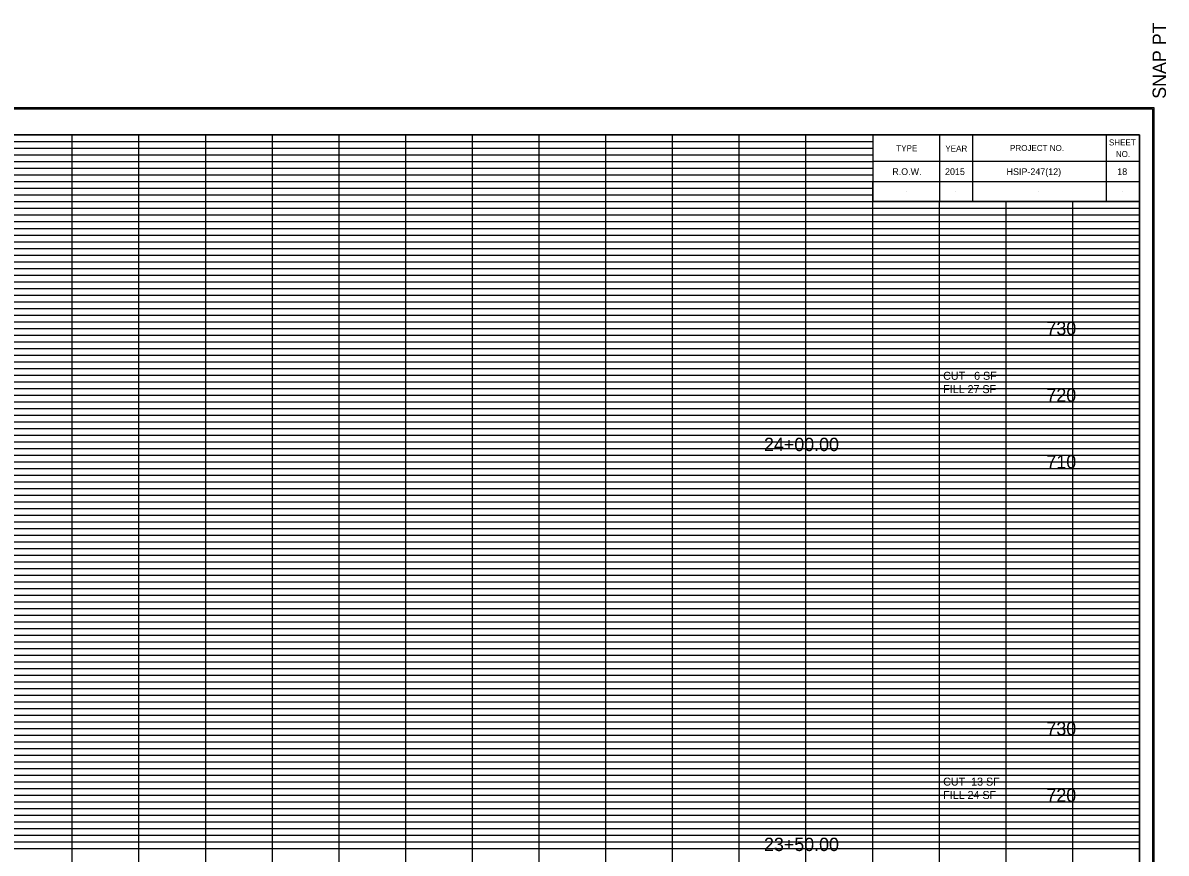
# Model space of a CAD drawing. Extents: x -200 to 1324, y -325 to 1497.
# Drawn here: x 1152.6 to 1324, y 1372.3 to 1496.8 of the extents above; entities that cross this region are included whole.
import ezdxf

# ---------------------------------------------------------------- set-up
doc = ezdxf.new("R2010")
doc.units = 0
for name, color, linetype in [('DESIGN - SCRATCH - User 1', 7, 'Continuous'), ('DESIGN - SHEET - Corner Text', 7, 'Continuous'), ('DESIGN - SHEET - Light Grid', 7, 'Continuous'), ('DESIGN - SHEET - Linework', 7, 'Continuous'), ('DESIGN - SHEET - Plot Shape', 7, 'Continuous'), ('DESIGN - TYPICAL - Text', 7, 'Continuous')]:
    doc.layers.add(name, color=color, linetype=linetype)

msp = doc.modelspace()

# ---------------------------------------------------------------- linework, layer by layer
at = {"layer": 'DESIGN - SCRATCH - User 1'}
for p, q in [((1285, 1474.5), (1285, 1474.5)), ((1292.4, 1474.5), (1292.4, 1474.5)), ((1304.9, 1474.5), (1304.9, 1474.5)), ((1317.4, 1474.5), (1317.4, 1474.5)), ((1285, 1471.5), (1285, 1471.5)), ((1292.4, 1471.5), (1292.4, 1471.5)), ((1304.9, 1471.5), (1304.9, 1471.5)), ((1317.4, 1471.5), (1317.4, 1471.5))]:
    msp.add_line(p, q, dxfattribs=at)
at = {"layer": 'DESIGN - SHEET - Light Grid'}
for p, q in [((1080, 1479), (1160, 1479)), ((1080, 1478), (1160, 1478)), ((1160, 1479), (1240, 1479)), ((1160, 1478), (1240, 1478)), ((1240, 1479), (1280, 1479)), ((1240, 1478), (1280, 1478)), ((1080, 1477), (1160, 1477)), ((1080, 1476), (1160, 1476)), ((1160, 1477), (1240, 1477)), ((1160, 1476), (1240, 1476)), ((1240, 1477), (1280, 1477)), ((1240, 1476), (1280, 1476)), ((1080, 1475), (1160, 1475)), ((1160, 1475), (1240, 1475)), ((1240, 1475), (1280, 1475)), ((1080, 1474), (1160, 1474)), ((1080, 1473), (1160, 1473)), ((1160, 1474), (1240, 1474)), ((1160, 1473), (1240, 1473)), ((1240, 1474), (1280, 1474)), ((1240, 1473), (1280, 1473)), ((1080, 1472), (1160, 1472)), ((1080, 1471), (1160, 1471)), ((1160, 1472), (1240, 1472)), ((1160, 1471), (1240, 1471)), ((1240, 1472), (1280, 1472)), ((1240, 1471), (1280, 1471)), ((1080, 1469), (1160, 1469)), ((1160, 1469), (1240, 1469)), ((1240, 1469), (1320, 1469)), ((1080, 1468), (1160, 1468)), ((1160, 1468), (1240, 1468)), ((1240, 1468), (1320, 1468)), ((1080, 1467), (1160, 1467)), ((1080, 1466), (1160, 1466)), ((1160, 1467), (1240, 1467)), ((1160, 1466), (1240, 1466)), ((1240, 1467), (1320, 1467)), ((1240, 1466), (1320, 1466)), ((1080, 1465), (1160, 1465)), ((1080, 1464), (1160, 1464)), ((1160, 1465), (1240, 1465)), ((1160, 1464), (1240, 1464)), ((1240, 1465), (1320, 1465)), ((1240, 1464), (1320, 1464)), ((1080, 1463), (1160, 1463)), ((1160, 1463), (1240, 1463)), ((1240, 1463), (1320, 1463)), ((1080, 1462), (1160, 1462)), ((1080, 1461), (1160, 1461)), ((1160, 1462), (1240, 1462)), ((1160, 1461), (1240, 1461)), ((1240, 1462), (1320, 1462)), ((1240, 1461), (1320, 1461)), ((1080, 1459), (1160, 1459)), ((1160, 1459), (1240, 1459)), ((1240, 1459), (1320, 1459)), ((1080, 1458), (1160, 1458)), ((1080, 1457), (1160, 1457)), ((1160, 1458), (1240, 1458)), ((1160, 1457), (1240, 1457)), ((1240, 1458), (1320, 1458)), ((1240, 1457), (1320, 1457)), ((1080, 1456), (1160, 1456)), ((1160, 1456), (1240, 1456)), ((1240, 1456), (1320, 1456)), ((1080, 1455), (1160, 1455)), ((1080, 1454), (1160, 1454)), ((1160, 1455), (1240, 1455)), ((1160, 1454), (1240, 1454)), ((1240, 1455), (1320, 1455)), ((1240, 1454), (1320, 1454)), ((1080, 1453), (1160, 1453)), ((1080, 1452), (1160, 1452)), ((1160, 1453), (1240, 1453)), ((1160, 1452), (1240, 1452)), ((1240, 1453), (1320, 1453)), ((1240, 1452), (1320, 1452)), ((1080, 1451), (1160, 1451)), ((1160, 1451), (1240, 1451)), ((1240, 1451), (1320, 1451)), ((1080, 1449), (1160, 1449)), ((1160, 1449), (1240, 1449)), ((1240, 1449), (1320, 1449)), ((1080, 1448), (1160, 1448)), ((1080, 1447), (1160, 1447)), ((1160, 1448), (1240, 1448)), ((1160, 1447), (1240, 1447)), ((1240, 1448), (1320, 1448)), ((1240, 1447), (1320, 1447)), ((1080, 1446), (1160, 1446)), ((1080, 1445), (1160, 1445)), ((1160, 1446), (1240, 1446)), ((1160, 1445), (1240, 1445)), ((1240, 1446), (1320, 1446)), ((1240, 1445), (1320, 1445)), ((1080, 1444), (1160, 1444)), ((1160, 1444), (1240, 1444)), ((1240, 1444), (1320, 1444)), ((1080, 1443), (1160, 1443)), ((1080, 1442), (1160, 1442)), ((1160, 1443), (1240, 1443)), ((1160, 1442), (1240, 1442)), ((1240, 1443), (1320, 1443)), ((1240, 1442), (1320, 1442)), ((1080, 1441), (1160, 1441)), ((1160, 1441), (1240, 1441)), ((1240, 1441), (1320, 1441)), ((1080, 1439), (1160, 1439)), ((1160, 1439), (1240, 1439)), ((1240, 1439), (1320, 1439)), ((1080, 1438), (1160, 1438)), ((1080, 1437), (1160, 1437)), ((1160, 1438), (1240, 1438)), ((1160, 1437), (1240, 1437)), ((1240, 1438), (1320, 1438)), ((1240, 1437), (1320, 1437)), ((1080, 1436), (1160, 1436)), ((1080, 1435), (1160, 1435)), ((1160, 1436), (1240, 1436)), ((1160, 1435), (1240, 1435)), ((1240, 1436), (1320, 1436)), ((1240, 1435), (1320, 1435)), ((1080, 1434), (1160, 1434)), ((1080, 1433), (1160, 1433)), ((1160, 1434), (1240, 1434)), ((1160, 1433), (1240, 1433)), ((1240, 1434), (1320, 1434)), ((1240, 1433), (1320, 1433)), ((1080, 1432), (1160, 1432)), ((1160, 1432), (1240, 1432)), ((1240, 1432), (1320, 1432)), ((1080, 1431), (1160, 1431)), ((1160, 1431), (1240, 1431)), ((1240, 1431), (1320, 1431)), ((1080, 1429), (1160, 1429)), ((1080, 1428), (1160, 1428)), ((1160, 1429), (1240, 1429)), ((1160, 1428), (1240, 1428)), ((1240, 1429), (1320, 1429)), ((1240, 1428), (1320, 1428)), ((1080, 1427), (1160, 1427)), ((1160, 1427), (1240, 1427)), ((1240, 1427), (1320, 1427)), ((1080, 1426), (1160, 1426)), ((1080, 1425), (1160, 1425)), ((1160, 1426), (1240, 1426)), ((1160, 1425), (1240, 1425)), ((1240, 1426), (1320, 1426)), ((1240, 1425), (1320, 1425)), ((1080, 1424), (1160, 1424)), ((1080, 1423), (1160, 1423)), ((1160, 1424), (1240, 1424)), ((1160, 1423), (1240, 1423)), ((1240, 1424), (1320, 1424)), ((1240, 1423), (1320, 1423)), ((1080, 1422), (1160, 1422)), ((1080, 1421), (1160, 1421)), ((1160, 1422), (1240, 1422)), ((1160, 1421), (1240, 1421)), ((1240, 1422), (1320, 1422)), ((1240, 1421), (1320, 1421)), ((1080, 1419), (1160, 1419)), ((1080, 1418), (1160, 1418)), ((1160, 1419), (1240, 1419)), ((1160, 1418), (1240, 1418)), ((1240, 1419), (1320, 1419)), ((1240, 1418), (1320, 1418)), ((1080, 1417), (1160, 1417)), ((1080, 1416), (1160, 1416)), ((1160, 1417), (1240, 1417)), ((1160, 1416), (1240, 1416)), ((1240, 1417), (1320, 1417)), ((1240, 1416), (1320, 1416)), ((1080, 1415), (1160, 1415)), ((1160, 1415), (1240, 1415)), ((1240, 1415), (1320, 1415)), ((1080, 1414), (1160, 1414)), ((1080, 1413), (1160, 1413)), ((1160, 1414), (1240, 1414)), ((1160, 1413), (1240, 1413)), ((1240, 1414), (1320, 1414)), ((1240, 1413), (1320, 1413)), ((1080, 1412), (1160, 1412)), ((1080, 1411), (1160, 1411)), ((1160, 1412), (1240, 1412)), ((1160, 1411), (1240, 1411)), ((1240, 1412), (1320, 1412)), ((1240, 1411), (1320, 1411)), ((1080, 1409), (1160, 1409)), ((1160, 1409), (1240, 1409)), ((1240, 1409), (1320, 1409)), ((1080, 1408), (1160, 1408)), ((1160, 1408), (1240, 1408)), ((1240, 1408), (1320, 1408)), ((1080, 1407), (1160, 1407)), ((1080, 1406), (1160, 1406)), ((1160, 1407), (1240, 1407)), ((1160, 1406), (1240, 1406)), ((1240, 1407), (1320, 1407)), ((1240, 1406), (1320, 1406)), ((1080, 1405), (1160, 1405)), ((1080, 1404), (1160, 1404)), ((1160, 1405), (1240, 1405)), ((1160, 1404), (1240, 1404)), ((1240, 1405), (1320, 1405)), ((1240, 1404), (1320, 1404)), ((1080, 1403), (1160, 1403)), ((1160, 1403), (1240, 1403)), ((1240, 1403), (1320, 1403)), ((1080, 1402), (1160, 1402)), ((1080, 1401), (1160, 1401)), ((1160, 1402), (1240, 1402)), ((1160, 1401), (1240, 1401)), ((1240, 1402), (1320, 1402)), ((1240, 1401), (1320, 1401)), ((1080, 1399), (1160, 1399)), ((1160, 1399), (1240, 1399)), ((1240, 1399), (1320, 1399)), ((1080, 1398), (1160, 1398)), ((1080, 1397), (1160, 1397)), ((1160, 1398), (1240, 1398)), ((1160, 1397), (1240, 1397)), ((1240, 1398), (1320, 1398)), ((1240, 1397), (1320, 1397)), ((1080, 1396), (1160, 1396)), ((1160, 1396), (1240, 1396)), ((1240, 1396), (1320, 1396)), ((1080, 1395), (1160, 1395)), ((1080, 1394), (1160, 1394)), ((1160, 1395), (1240, 1395)), ((1160, 1394), (1240, 1394)), ((1240, 1395), (1320, 1395)), ((1240, 1394), (1320, 1394)), ((1080, 1393), (1160, 1393)), ((1080, 1392), (1160, 1392)), ((1160, 1393), (1240, 1393)), ((1160, 1392), (1240, 1392)), ((1240, 1393), (1320, 1393)), ((1240, 1392), (1320, 1392)), ((1080, 1391), (1160, 1391)), ((1160, 1391), (1240, 1391)), ((1240, 1391), (1320, 1391)), ((1080, 1389), (1160, 1389)), ((1160, 1389), (1240, 1389)), ((1240, 1389), (1320, 1389)), ((1080, 1388), (1160, 1388)), ((1080, 1387), (1160, 1387)), ((1160, 1388), (1240, 1388)), ((1160, 1387), (1240, 1387)), ((1240, 1388), (1320, 1388)), ((1240, 1387), (1320, 1387)), ((1080, 1386), (1160, 1386)), ((1080, 1385), (1160, 1385)), ((1160, 1386), (1240, 1386)), ((1160, 1385), (1240, 1385)), ((1240, 1386), (1320, 1386)), ((1240, 1385), (1320, 1385)), ((1080, 1384), (1160, 1384)), ((1160, 1384), (1240, 1384)), ((1240, 1384), (1320, 1384)), ((1080, 1383), (1160, 1383)), ((1080, 1382), (1160, 1382)), ((1160, 1383), (1240, 1383)), ((1160, 1382), (1240, 1382)), ((1240, 1383), (1320, 1383)), ((1240, 1382), (1320, 1382)), ((1080, 1381), (1160, 1381)), ((1160, 1381), (1240, 1381)), ((1240, 1381), (1320, 1381)), ((1080, 1379), (1160, 1379)), ((1160, 1379), (1240, 1379)), ((1240, 1379), (1320, 1379)), ((1080, 1378), (1160, 1378)), ((1080, 1377), (1160, 1377)), ((1160, 1378), (1240, 1378)), ((1160, 1377), (1240, 1377)), ((1240, 1378), (1320, 1378)), ((1240, 1377), (1320, 1377)), ((1080, 1376), (1160, 1376)), ((1080, 1375), (1160, 1375)), ((1160, 1376), (1240, 1376)), ((1160, 1375), (1240, 1375)), ((1240, 1376), (1320, 1376)), ((1240, 1375), (1320, 1375)), ((1080, 1374), (1160, 1374)), ((1080, 1373), (1160, 1373)), ((1160, 1374), (1240, 1374)), ((1160, 1373), (1240, 1373)), ((1240, 1374), (1320, 1374)), ((1240, 1373), (1320, 1373))]:
    msp.add_line(p, q, dxfattribs=at)
at = {"layer": 'DESIGN - SHEET - Linework'}
for p, q in [((981.77, 1484.14), (1322.17, 1484.14)), ((1322.17, 1484.14), (1322.17, 1265.86)), ((1160, 1270), (1160, 1480)), ((1170, 1270), (1170, 1480)), ((1180, 1270), (1180, 1480)), ((1190, 1270), (1190, 1480)), ((1200, 1270), (1200, 1480)), ((1210, 1270), (1210, 1480)), ((1220, 1270), (1220, 1480)), ((1230, 1270), (1230, 1480)), ((1240, 1270), (1240, 1480)), ((1250, 1270), (1250, 1480)), ((1260, 1270), (1260, 1480)), ((1270, 1270), (1270, 1480)), ((1000, 1470), (1280, 1470)), ((1280, 1270), (1280, 1470)), ((1290, 1270), (1290, 1470)), ((1300, 1270), (1300, 1470)), ((1310, 1270), (1310, 1470)), ((1000, 1460), (1320, 1460)), ((1000, 1450), (1320, 1450)), ((1000, 1440), (1320, 1440)), ((1000, 1430), (1320, 1430)), ((1000, 1420), (1320, 1420)), ((1000, 1410), (1320, 1410)), ((1000, 1400), (1320, 1400)), ((1000, 1390), (1320, 1390)), ((1000, 1380), (1320, 1380))]:
    msp.add_line(p, q, dxfattribs=at)
for points in [[(1000, 1480), (1000, 1270), (1320, 1270), (1320, 1480), (1000, 1480)], [(1280, 1480), (1280, 1470), (1320, 1470), (1320, 1480), (1315, 1480), (1315, 1470), (1295, 1470), (1295, 1480), (1290, 1480), (1290, 1470), (1320, 1470), (1280, 1470), (1280, 1473), (1320, 1473), (1320, 1476), (1280, 1476)]]:
    msp.add_lwpolyline(points, dxfattribs=at)
at = {"layer": 'DESIGN - SHEET - Plot Shape'}
for points in [[(981.97, 1483.94), (1321.97, 1483.94), (1321.97, 1266.06), (981.97, 1266.06)], [(991.5, 1480), (1320, 1480), (1320, 1267.5), (991.5, 1267.5)]]:
    msp.add_lwpolyline(points, close=True, dxfattribs=at)

# ---------------------------------------------------------------- texts
at = {"layer": 'DESIGN - SHEET - Corner Text'}
msp.add_text('  SNAP PT', height=2, rotation=90, dxfattribs=at).set_placement((1323.97, 1483.94))
for s, height, p in [('SHEET', 0.9, (1315.43, 1478.43)), ('TYPE', 0.9, (1283.54, 1477.56)), ('YEAR', 0.9, (1290.9, 1477.52)), ('PROJECT NO.', 0.9, (1300.6, 1477.6)), ('NO.', 0.9, (1316.46, 1476.69)), ('R.O.W.', 1, (1282.94, 1474)), ('2015', 1, (1290.85, 1474)), ('HSIP-247(12)', 1, (1300.08, 1474)), ('18', 1, (1316.67, 1474))]:
    msp.add_text(s, height=height, dxfattribs=at).set_placement(p)
at = {"layer": 'DESIGN - TYPICAL - Text'}
for s, height, p in [('     730     ', 2, (1302.34, 1450)), ('CUT   6 SF', 1.2, (1290.57, 1443.29)), ('FILL 27 SF', 1.2, (1290.57, 1441.29)), ('     720     ', 2, (1302.34, 1440)), ('     24+00.00     ', 2, (1260, 1432.6)), ('     710     ', 2, (1302.34, 1430)), ('     730     ', 2, (1302.34, 1390)), ('CUT  13 SF', 1.2, (1290.57, 1382.44)), ('FILL 24 SF', 1.2, (1290.57, 1380.44)), ('     720     ', 2, (1302.34, 1380)), ('     23+50.00     ', 2, (1260, 1372.63))]:
    msp.add_text(s, height=height, dxfattribs=at).set_placement(p)

doc.saveas('drawing.dxf')
